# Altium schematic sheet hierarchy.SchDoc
size A3; DocumentNumber: 1; SheetNumber: 1; SheetTotal: 15; SheetDescription: Overview
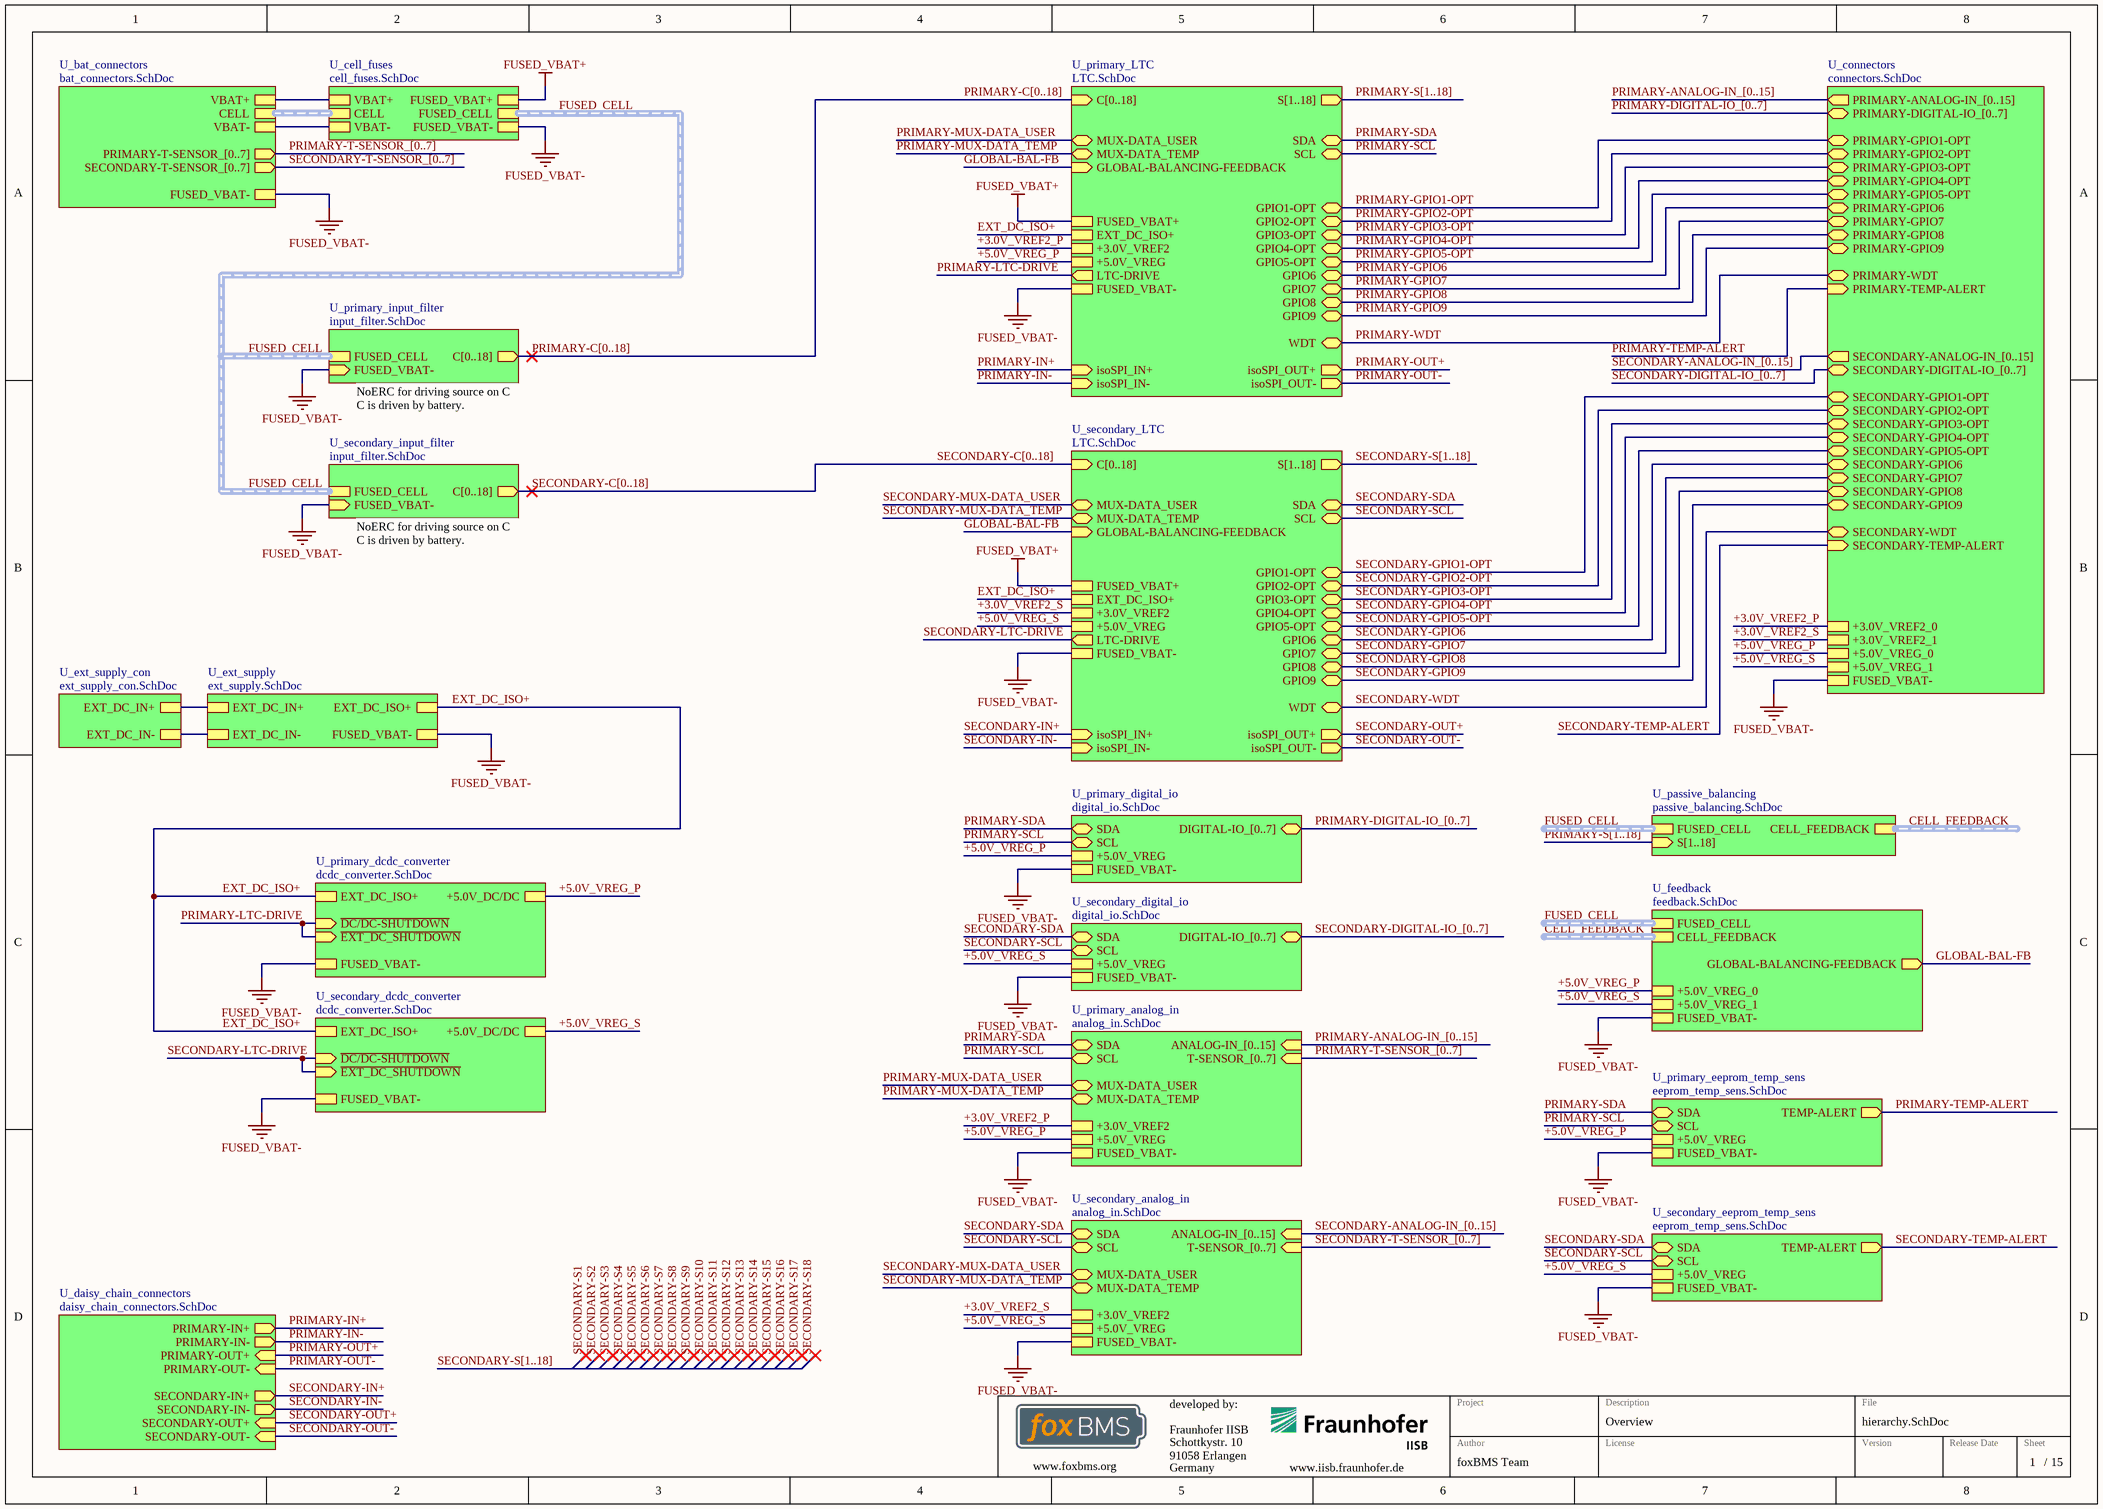
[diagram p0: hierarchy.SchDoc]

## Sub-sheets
U_bat_connectors = bat_connectors.SchDoc: CELL (harness CELL_VOLTAGES), PRIMARY-T-SENSOR_[0..7] (out), SECONDARY-T-SENSOR_[0..7] (out), VBAT+, VBAT-, FUSED_VBAT-
U_cell_fuses = cell_fuses.SchDoc: FUSED_CELL (harness CELL_VOLTAGES), CELL (harness CELL_VOLTAGES), VBAT+, VBAT-, FUSED_VBAT+, FUSED_VBAT-
U_connectors = connectors.SchDoc: PRIMARY-WDT (bidir), SECONDARY-WDT (bidir), PRIMARY-GPIO1-OPT (bidir), PRIMARY-GPIO2-OPT (bidir), PRIMARY-GPIO3-OPT (bidir), PRIMARY-GPIO4-OPT (bidir), PRIMARY-GPIO5-OPT (bidir), SECONDARY-GPIO1-OPT (bidir), SECONDARY-GPIO2-OPT (bidir), SECONDARY-GPIO3-OPT (bidir), SECONDARY-GPIO4-OPT (bidir), SECONDARY-GPIO5-OPT (bidir), PRIMARY-TEMP-ALERT (in), SECONDARY-TEMP-ALERT (in), SECONDARY-DIGITAL-IO_[0..7] (bidir), PRIMARY-DIGITAL-IO_[0..7] (bidir), PRIMARY-ANALOG-IN_[0..15] (out), SECONDARY-ANALOG-IN_[0..15] (out), PRIMARY-GPIO9 (bidir), PRIMARY-GPIO7 (bidir), PRIMARY-GPIO6 (bidir), PRIMARY-GPIO8 (bidir), SECONDARY-GPIO9 (bidir), SECONDARY-GPIO8 (bidir), SECONDARY-GPIO7 (bidir), SECONDARY-GPIO6 (bidir), +3.0V_VREF2_1, +5.0V_VREG_1, +3.0V_VREF2_0, FUSED_VBAT-, +5.0V_VREG_0
U_daisy_chain_connectors = daisy_chain_connectors.SchDoc: SECONDARY-IN+ (out), SECONDARY-IN- (out), SECONDARY-OUT+ (in), SECONDARY-OUT- (in), PRIMARY-IN+ (out), PRIMARY-IN- (out), PRIMARY-OUT- (in), PRIMARY-OUT+ (in)
U_ext_supply = ext_supply.SchDoc: EXT_DC_IN+, EXT_DC_IN-, EXT_DC_ISO+, FUSED_VBAT-
U_ext_supply_con = ext_supply_con.SchDoc: EXT_DC_IN+, EXT_DC_IN-
U_feedback = feedback.SchDoc: GLOBAL-BALANCING-FEEDBACK (out), CELL_FEEDBACK (harness CELL_FEEDBACK), FUSED_CELL (harness CELL_VOLTAGES), +5.0V_VREG_1, +5.0V_VREG_0, FUSED_VBAT-
U_passive_balancing = passive_balancing.SchDoc: FUSED_CELL (harness CELL_VOLTAGES), S[1..18] (in), CELL_FEEDBACK (harness CELL_FEEDBACK)
U_primary_analog_in = analog_in.SchDoc: MUX-DATA_TEMP (bidir), MUX-DATA_USER (bidir), ANALOG-IN_[0..15] (in), T-SENSOR_[0..7] (in), SCL (bidir), SDA (bidir), +5.0V_VREG, FUSED_VBAT-, +3.0V_VREF2
U_primary_dcdc_converter = dcdc_converter.SchDoc: +5.0V_DC/DC, FUSED_VBAT-, ~{DC/DC-SHUTDOWN} (in), EXT_DC_ISO+, ~{EXT_DC_SHUTDOWN} (in)
U_primary_digital_io = digital_io.SchDoc: SCL (bidir), SDA (bidir), DIGITAL-IO_[0..7] (bidir), +5.0V_VREG, FUSED_VBAT-
U_primary_eeprom_temp_sens = eeprom_temp_sens.SchDoc: TEMP-ALERT (out), SDA (bidir), SCL (bidir), FUSED_VBAT-, +5.0V_VREG
U_primary_input_filter = input_filter.SchDoc: FUSED_CELL (harness CELL_VOLTAGES), C[0..18] (out), FUSED_VBAT- (in)
U_primary_LTC = LTC.SchDoc: isoSPI_IN- (in), isoSPI_IN+ (in), isoSPI_OUT- (out), isoSPI_OUT+ (out), GPIO5-OPT (bidir), GPIO4-OPT (bidir), MUX-DATA_USER (bidir), GPIO1-OPT (bidir), SCL (bidir), GPIO2-OPT (bidir), MUX-DATA_TEMP (bidir), GPIO3-OPT (bidir), GLOBAL-BALANCING-FEEDBACK (in), SDA (bidir), EXT_DC_ISO+, C[0..18] (in), S[1..18] (out), WDT (bidir), GPIO8 (bidir), GPIO7 (bidir), GPIO9 (bidir), GPIO6 (bidir), FUSED_VBAT+, FUSED_VBAT-, +5.0V_VREG, +3.0V_VREF2, LTC-DRIVE (out)
U_secondary_analog_in = analog_in.SchDoc: MUX-DATA_TEMP (bidir), MUX-DATA_USER (bidir), ANALOG-IN_[0..15] (in), T-SENSOR_[0..7] (in), SCL (bidir), SDA (bidir), +5.0V_VREG, FUSED_VBAT-, +3.0V_VREF2
U_secondary_dcdc_converter = dcdc_converter.SchDoc: +5.0V_DC/DC, FUSED_VBAT-, ~{DC/DC-SHUTDOWN} (in), EXT_DC_ISO+, ~{EXT_DC_SHUTDOWN} (in)
U_secondary_digital_io = digital_io.SchDoc: SCL (bidir), SDA (bidir), DIGITAL-IO_[0..7] (bidir), +5.0V_VREG, FUSED_VBAT-
U_secondary_eeprom_temp_sens = eeprom_temp_sens.SchDoc: TEMP-ALERT (out), SDA (bidir), SCL (bidir), FUSED_VBAT-, +5.0V_VREG
U_secondary_input_filter = input_filter.SchDoc: FUSED_CELL (harness CELL_VOLTAGES), C[0..18] (out), FUSED_VBAT- (in)
U_secondary_LTC = LTC.SchDoc: isoSPI_IN- (in), isoSPI_IN+ (in), isoSPI_OUT- (out), isoSPI_OUT+ (out), GPIO5-OPT (bidir), GPIO4-OPT (bidir), MUX-DATA_USER (bidir), GPIO1-OPT (bidir), SCL (bidir), GPIO2-OPT (bidir), MUX-DATA_TEMP (bidir), GPIO3-OPT (bidir), GLOBAL-BALANCING-FEEDBACK (in), SDA (bidir), EXT_DC_ISO+, C[0..18] (in), S[1..18] (out), WDT (bidir), GPIO8 (bidir), GPIO7 (bidir), GPIO9 (bidir), GPIO6 (bidir), FUSED_VBAT+, FUSED_VBAT-, +5.0V_VREG, +3.0V_VREF2, LTC-DRIVE (out)

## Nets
FUSED_VBAT+: sheet U_cell_fuses/FUSED_VBAT+, sheet U_primary_LTC/FUSED_VBAT+, sheet U_secondary_LTC/FUSED_VBAT+
FUSED_VBAT-: sheet U_cell_fuses/FUSED_VBAT-, sheet U_primary_input_filter/FUSED_VBAT-, sheet U_secondary_input_filter/FUSED_VBAT-, sheet U_ext_supply/FUSED_VBAT-, sheet U_connectors/FUSED_VBAT-, sheet U_feedback/FUSED_VBAT-, sheet U_primary_LTC/FUSED_VBAT-, sheet U_secondary_digital_io/FUSED_VBAT-, sheet U_secondary_eeprom_temp_sens/FUSED_VBAT-, sheet U_secondary_analog_in/FUSED_VBAT-, sheet U_bat_connectors/FUSED_VBAT-, sheet U_primary_dcdc_converter/FUSED_VBAT-, sheet U_secondary_dcdc_converter/FUSED_VBAT-, sheet U_secondary_LTC/FUSED_VBAT-, sheet U_primary_digital_io/FUSED_VBAT-, sheet U_primary_eeprom_temp_sens/FUSED_VBAT-, sheet U_primary_analog_in/FUSED_VBAT-
+3.0V_VREF2_P: sheet U_connectors/+3.0V_VREF2_0, sheet U_primary_LTC/+3.0V_VREF2, sheet U_primary_analog_in/+3.0V_VREF2
+3.0V_VREF2_S: sheet U_connectors/+3.0V_VREF2_1, sheet U_secondary_analog_in/+3.0V_VREF2, sheet U_secondary_LTC/+3.0V_VREF2
+5.0V_VREG_P: sheet U_connectors/+5.0V_VREG_0, sheet U_feedback/+5.0V_VREG_0, sheet U_primary_LTC/+5.0V_VREG, sheet U_primary_dcdc_converter/+5.0V_DC/DC, sheet U_primary_digital_io/+5.0V_VREG, sheet U_primary_eeprom_temp_sens/+5.0V_VREG, sheet U_primary_analog_in/+5.0V_VREG
+5.0V_VREG_S: sheet U_connectors/+5.0V_VREG_1, sheet U_feedback/+5.0V_VREG_1, sheet U_secondary_digital_io/+5.0V_VREG, sheet U_secondary_eeprom_temp_sens/+5.0V_VREG, sheet U_secondary_analog_in/+5.0V_VREG, sheet U_secondary_dcdc_converter/+5.0V_DC/DC, sheet U_secondary_LTC/+5.0V_VREG
EXT_DC_ISO+: sheet U_ext_supply/EXT_DC_ISO+, sheet U_primary_LTC/EXT_DC_ISO+, sheet U_primary_dcdc_converter/EXT_DC_ISO+, sheet U_secondary_dcdc_converter/EXT_DC_ISO+, sheet U_secondary_LTC/EXT_DC_ISO+
GLOBAL-BAL-FB: sheet U_feedback/GLOBAL-BALANCING-FEEDBACK, sheet U_primary_LTC/GLOBAL-BALANCING-FEEDBACK, sheet U_secondary_LTC/GLOBAL-BALANCING-FEEDBACK
PRIMARY-GPIO1-OPT: sheet U_connectors/PRIMARY-GPIO1-OPT, sheet U_primary_LTC/GPIO1-OPT
PRIMARY-GPIO2-OPT: sheet U_connectors/PRIMARY-GPIO2-OPT, sheet U_primary_LTC/GPIO2-OPT
PRIMARY-GPIO3-OPT: sheet U_connectors/PRIMARY-GPIO3-OPT, sheet U_primary_LTC/GPIO3-OPT
PRIMARY-GPIO4-OPT: sheet U_connectors/PRIMARY-GPIO4-OPT, sheet U_primary_LTC/GPIO4-OPT
PRIMARY-GPIO5-OPT: sheet U_connectors/PRIMARY-GPIO5-OPT, sheet U_primary_LTC/GPIO5-OPT
PRIMARY-GPIO6: sheet U_connectors/PRIMARY-GPIO6, sheet U_primary_LTC/GPIO6
PRIMARY-GPIO7: sheet U_connectors/PRIMARY-GPIO7, sheet U_primary_LTC/GPIO7
PRIMARY-GPIO8: sheet U_connectors/PRIMARY-GPIO8, sheet U_primary_LTC/GPIO8
PRIMARY-GPIO9: sheet U_connectors/PRIMARY-GPIO9, sheet U_primary_LTC/GPIO9
PRIMARY-IN+: sheet U_primary_LTC/isoSPI_IN+, sheet U_daisy_chain_connectors/PRIMARY-IN+
PRIMARY-IN-: sheet U_primary_LTC/isoSPI_IN-, sheet U_daisy_chain_connectors/PRIMARY-IN-
PRIMARY-LTC-DRIVE: sheet U_primary_LTC/LTC-DRIVE, sheet U_primary_dcdc_converter/~{DC/DC-SHUTDOWN}, sheet U_primary_dcdc_converter/~{EXT_DC_SHUTDOWN}
PRIMARY-MUX-DATA_TEMP: sheet U_primary_LTC/MUX-DATA_TEMP, sheet U_primary_analog_in/MUX-DATA_TEMP
PRIMARY-MUX-DATA_USER: sheet U_primary_LTC/MUX-DATA_USER, sheet U_primary_analog_in/MUX-DATA_USER
PRIMARY-OUT+: sheet U_primary_LTC/isoSPI_OUT+, sheet U_daisy_chain_connectors/PRIMARY-OUT+
PRIMARY-OUT-: sheet U_primary_LTC/isoSPI_OUT-, sheet U_daisy_chain_connectors/PRIMARY-OUT-
PRIMARY-SCL: sheet U_primary_LTC/SCL, sheet U_primary_digital_io/SCL, sheet U_primary_eeprom_temp_sens/SCL, sheet U_primary_analog_in/SCL
PRIMARY-SDA: sheet U_primary_LTC/SDA, sheet U_primary_digital_io/SDA, sheet U_primary_eeprom_temp_sens/SDA, sheet U_primary_analog_in/SDA
PRIMARY-TEMP-ALERT: sheet U_connectors/PRIMARY-TEMP-ALERT, sheet U_primary_eeprom_temp_sens/TEMP-ALERT
PRIMARY-WDT: sheet U_connectors/PRIMARY-WDT, sheet U_primary_LTC/WDT
SECONDARY-GPIO1-OPT: sheet U_connectors/SECONDARY-GPIO1-OPT, sheet U_secondary_LTC/GPIO1-OPT
SECONDARY-GPIO2-OPT: sheet U_connectors/SECONDARY-GPIO2-OPT, sheet U_secondary_LTC/GPIO2-OPT
SECONDARY-GPIO3-OPT: sheet U_connectors/SECONDARY-GPIO3-OPT, sheet U_secondary_LTC/GPIO3-OPT
SECONDARY-GPIO4-OPT: sheet U_connectors/SECONDARY-GPIO4-OPT, sheet U_secondary_LTC/GPIO4-OPT
SECONDARY-GPIO5-OPT: sheet U_connectors/SECONDARY-GPIO5-OPT, sheet U_secondary_LTC/GPIO5-OPT
SECONDARY-GPIO6: sheet U_connectors/SECONDARY-GPIO6, sheet U_secondary_LTC/GPIO6
SECONDARY-GPIO7: sheet U_connectors/SECONDARY-GPIO7, sheet U_secondary_LTC/GPIO7
SECONDARY-GPIO8: sheet U_connectors/SECONDARY-GPIO8, sheet U_secondary_LTC/GPIO8
SECONDARY-GPIO9: sheet U_connectors/SECONDARY-GPIO9, sheet U_secondary_LTC/GPIO9
SECONDARY-IN+: sheet U_daisy_chain_connectors/SECONDARY-IN+, sheet U_secondary_LTC/isoSPI_IN+
SECONDARY-IN-: sheet U_daisy_chain_connectors/SECONDARY-IN-, sheet U_secondary_LTC/isoSPI_IN-
SECONDARY-LTC-DRIVE: sheet U_secondary_dcdc_converter/~{DC/DC-SHUTDOWN}, sheet U_secondary_dcdc_converter/~{EXT_DC_SHUTDOWN}, sheet U_secondary_LTC/LTC-DRIVE
SECONDARY-MUX-DATA_TEMP: sheet U_secondary_analog_in/MUX-DATA_TEMP, sheet U_secondary_LTC/MUX-DATA_TEMP
SECONDARY-MUX-DATA_USER: sheet U_secondary_analog_in/MUX-DATA_USER, sheet U_secondary_LTC/MUX-DATA_USER
SECONDARY-OUT+: sheet U_daisy_chain_connectors/SECONDARY-OUT+, sheet U_secondary_LTC/isoSPI_OUT+
SECONDARY-OUT-: sheet U_daisy_chain_connectors/SECONDARY-OUT-, sheet U_secondary_LTC/isoSPI_OUT-
SECONDARY-SCL: sheet U_secondary_digital_io/SCL, sheet U_secondary_eeprom_temp_sens/SCL, sheet U_secondary_analog_in/SCL, sheet U_secondary_LTC/SCL
SECONDARY-SDA: sheet U_secondary_digital_io/SDA, sheet U_secondary_eeprom_temp_sens/SDA, sheet U_secondary_analog_in/SDA, sheet U_secondary_LTC/SDA
SECONDARY-TEMP-ALERT: sheet U_connectors/SECONDARY-TEMP-ALERT, sheet U_secondary_eeprom_temp_sens/TEMP-ALERT
SECONDARY-WDT: sheet U_connectors/SECONDARY-WDT, sheet U_secondary_LTC/WDT
(unnamed): sheet U_cell_fuses/VBAT+, sheet U_bat_connectors/VBAT+
(unnamed): sheet U_cell_fuses/VBAT-, sheet U_bat_connectors/VBAT-  [a separate net that carries the same name]
(unnamed): sheet U_ext_supply/EXT_DC_IN+, sheet U_ext_supply_con/EXT_DC_IN+  [a separate net that carries the same name]
(unnamed): sheet U_ext_supply/EXT_DC_IN-, sheet U_ext_supply_con/EXT_DC_IN-  [a separate net that carries the same name]

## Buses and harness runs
bus PRIMARY-ANALOG-IN_[0..15] = sheet U_connectors/PRIMARY-ANALOG-IN_[0..15]
bus PRIMARY-ANALOG-IN_[0..15] = sheet U_primary_analog_in/ANALOG-IN_[0..15]
bus PRIMARY-C[0..18] = sheet U_primary_input_filter/C[0..18] = sheet U_primary_LTC/C[0..18]
bus PRIMARY-DIGITAL-IO_[0..7] = sheet U_connectors/PRIMARY-DIGITAL-IO_[0..7]
bus PRIMARY-DIGITAL-IO_[0..7] = sheet U_primary_digital_io/DIGITAL-IO_[0..7]
bus PRIMARY-S[1..18] = sheet U_passive_balancing/S[1..18]
bus PRIMARY-S[1..18] = sheet U_primary_LTC/S[1..18]
bus PRIMARY-T-SENSOR_[0..7] = sheet U_bat_connectors/PRIMARY-T-SENSOR_[0..7]
bus PRIMARY-T-SENSOR_[0..7] = sheet U_primary_analog_in/T-SENSOR_[0..7]
bus SECONDARY-ANALOG-IN_[0..15] = sheet U_connectors/SECONDARY-ANALOG-IN_[0..15]
bus SECONDARY-ANALOG-IN_[0..15] = sheet U_secondary_analog_in/ANALOG-IN_[0..15]
bus SECONDARY-C[0..18] = sheet U_secondary_input_filter/C[0..18] = sheet U_secondary_LTC/C[0..18]
bus SECONDARY-DIGITAL-IO_[0..7] = sheet U_connectors/SECONDARY-DIGITAL-IO_[0..7]
bus SECONDARY-DIGITAL-IO_[0..7] = sheet U_secondary_digital_io/DIGITAL-IO_[0..7]
bus SECONDARY-S[1..18]
bus SECONDARY-S[1..18] = sheet U_secondary_LTC/S[1..18]
bus SECONDARY-T-SENSOR_[0..7] = sheet U_bat_connectors/SECONDARY-T-SENSOR_[0..7]
bus SECONDARY-T-SENSOR_[0..7] = sheet U_secondary_analog_in/T-SENSOR_[0..7]
harness CELL_FEEDBACK = sheet U_feedback/CELL_FEEDBACK
harness CELL_FEEDBACK = sheet U_passive_balancing/CELL_FEEDBACK
harness FUSED_CELL = sheet U_cell_fuses/FUSED_CELL = sheet U_primary_input_filter/FUSED_CELL = sheet U_secondary_input_filter/FUSED_CELL
harness FUSED_CELL = sheet U_feedback/FUSED_CELL
harness FUSED_CELL = sheet U_passive_balancing/FUSED_CELL
harness sheet U_bat_connectors/CELL = sheet U_cell_fuses/CELL

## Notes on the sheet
- NoERC for driving source on C
  C is driven by battery.
- Labels drawn without touching a wire or pin: SECONDARY-S1, SECONDARY-S2, SECONDARY-S3, SECONDARY-S4, SECONDARY-S5, SECONDARY-S6, SECONDARY-S7, SECONDARY-S8, SECONDARY-S9, SECONDARY-S10, SECONDARY-S11, SECONDARY-S12, SECONDARY-S13, SECONDARY-S14, SECONDARY-S15, SECONDARY-S16, SECONDARY-S17, SECONDARY-S18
